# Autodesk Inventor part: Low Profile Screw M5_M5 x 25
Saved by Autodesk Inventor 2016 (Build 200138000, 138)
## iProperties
Created: 2016-03
Part Number: Low Profile Screw M5_M5 x 25
Material: Generic
Document SubType Name: Modeling
Designer: bongo_000
Density: 1 g/cm^3
Appearance: Default
Author: bongo_000
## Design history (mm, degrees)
feature "CUT-EXTRUDE2"
body "Solid1"
